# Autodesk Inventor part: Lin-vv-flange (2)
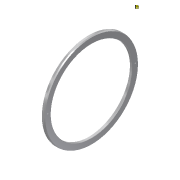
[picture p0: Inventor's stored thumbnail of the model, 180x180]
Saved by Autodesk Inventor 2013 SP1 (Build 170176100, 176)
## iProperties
Created: 2012-11
Part Number: Lin-vv-flange (2)
Material: Stainless Steel, 304
Description: VACUUM VESSEL FLANGE
Document SubType Name: Modeling
Designer: Henneborn
Manufacturer: Standard
Standards Organization: Custom
Mass: 58572.8 g
Surface Area: 6586.56 cm^2
Volume: 7414.28 cm^3
Density: 7.9 g/cm^3
Rohmasse: 42,5" O.D. x 1,5" made of sheet
Author: vm
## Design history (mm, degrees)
sketch "Sketch1"
  geometry: L1 (-7.366, 0)-(44.196, 0) reference; L2 (0, -108.712)-(0, 652.272) reference; L3 (0, 543.56)-(36.83, 543.56); L4 (36.83, 543.56)-(36.83, 482.798); L5 (30.48, 473.075)-(0, 473.075); L6 (0, 473.075)-(0, 543.56); L7 (30.48, 473.075)-(30.48, 482.798); L8 (30.48, 482.798)-(36.83, 482.798); 1 further point
  constraints: 12 end point, 2 parallel, 2 perpendicular, 1 horizontal, 1 point on line
  dimensions: "d0" = 543.56 distance between parallel lines of L1 L3; "d1" = 36.83 distance between parallel lines of L4 L6; "d22" = 473.075 distance between parallel lines of L1 L5; "d23" = 482.79844 distance between parallel lines of L1 L8; "d27" = 6.35 distance between parallel lines of L4 L7
revolve "Revolution1" sketch "Sketch1" stored, may be unused: angle "d6" = 90 deg
chamfer "Chamfer2" distance "d28" = 3.81; stored, may be unused: second distance "d29" = 3.175, angle "d30" = 45 deg
workplane "Work Plane4"
sketch "Sketch9"
  geometry: L1 (0, -668.924)-(0, 702.022) reference; C1 r 473.075 at (0, 0) reference; 1 further point
  dimensions: "d140" = 510.54 distance of C1.centre point (66.639, 506.172)
hole "Hole6" sketch "Sketch9" at (66.639, 506.172) diameter "d93" = 12.7508; stored, may be unused: countersink angle "d97" = 82 deg, drill point angle "d99" = 118 deg; dims "d94" = 21.59, "d95" = 9.525, "d96" = 6.35, "d98" = 27.94
workplane "Work Plane3"
sketch "Sketch11"
  geometry: C1 r 543.56 at (0, 0) reference; 2 further points
  dimensions: "d135" = 508 horizontal distance of point (-508, 25.4) C1.centre; "d136" = 25.4 vertical distance of C1.centre point (-508, 25.4); "d137" = 508 horizontal distance of point (508, 25.4) C1.centre; "d138" = 25.4 vertical distance of point (508, 25.4) C1.centre
hole "Hole8" sketch "Sketch11" at (-508, 25.4), (508, 25.4) diameter "d118" = 12.6873; stored, may be unused: countersink angle "d122" = 82 deg, drill point angle "d124" = 118 deg; dims "d119" = 19.05, "d120" = 9.525, "d121" = 6.35, "d123" = 20.32
chamfer "Chamfer6" distance "d125" = 2.54; stored, may be unused: second distance "d126" = 3.175, angle "d127" = 45 deg
chamfer "Chamfer7" distance "d128" = 12.7; stored, may be unused: second distance "d129" = 5.08, angle "d130" = 45 deg
body "Solid1"
pattern_circular "Circular Pattern7" dims angle "d133" = 360 deg
